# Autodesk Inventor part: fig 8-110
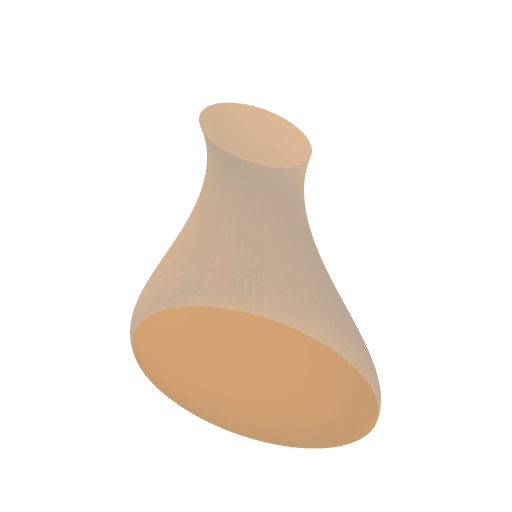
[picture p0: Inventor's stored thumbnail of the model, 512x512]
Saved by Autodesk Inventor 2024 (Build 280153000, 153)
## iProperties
Created: 2004-05
Part Number: fig 8-110
Document SubType Name: Modeling
Designer: CADCIM Technologies
Manufacturer: Standard
Standards Organization: Custom
Density: 1 g/cm^3
Material: Generic
Appearance: Default
Author: CADCIM Technologies
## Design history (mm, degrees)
sketch "Sketch4"
  geometry: 1 further point; 1 other entity
  constraints: 2 other
workplane "Work Plane2"
sketch "Sketch5"
  geometry: 1 further point; 1 other entity
  constraints: 2 other
feature "LoftSrf1" sketch "Sketch5" dims "d4" = 20, "d5" = 110 deg, "d6" = 40, "d7" = 70 deg
patch "Boundary Patch1" dims "d8" = 0, "d9" = 0
patch "Boundary Patch2" dims "d10" = 0, "d11" = 0
patch "Boundary Patch3" dims "d12" = 0, "d13" = 0
body "Srf1"
body "Srf2"
body "Srf3"
body "Srf4"
other parameters: "d3" = 33.5
